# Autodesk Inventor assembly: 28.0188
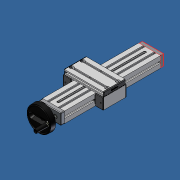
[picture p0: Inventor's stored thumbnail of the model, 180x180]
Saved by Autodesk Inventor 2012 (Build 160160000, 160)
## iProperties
Created: 2007-06
Part Number: 28.0188
Document SubType Name: Assembly
Designer: Andy Moles
Description: ADJUSTING UNIT VEN 45X90 F
Author: Andy Moles
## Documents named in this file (19)
- C:\Andys Backup Data\ANDY'S INVENTOR\INVENTOR LIBRARIES\PARTS LIBRARY\READY FOR USE MODULES LG\28.0188 ADJUSTING UNIT VEN 45X90 F.iam
- C:\Andys Backup Data\ANDY'S INVENTOR\INVENTOR LIBRARIES\PARTS LIBRARY\READY FOR USE MODULES LG\SUBCOMPONENTS\28.0200 BEARING PLATE 45X90 HANDWHEEL SIDE.ipt
- C:\Andys Backup Data\ANDY'S INVENTOR\INVENTOR LIBRARIES\PARTS LIBRARY\READY FOR USE MODULES LG\SUBCOMPONENTS\50.1264 BALL BEARING 10X30X9 6200 2RS DIN 625.ipt
- C:\Andys Backup Data\ANDY'S INVENTOR\INVENTOR LIBRARIES\PARTS LIBRARY\READY FOR USE MODULES LG\SUBCOMPONENTS\28.0201 BEARING PLATE 45X90 IDLER SIDE.ipt
- C:\Andys Backup Data\ANDY'S INVENTOR\INVENTOR LIBRARIES\PARTS LIBRARY\READY FOR USE MODULES LG\SUBCOMPONENTS\28.0204 HANDWHEEL 100mm.iam
- C:\Andys Backup Data\ANDY'S INVENTOR\INVENTOR LIBRARIES\PARTS LIBRARY\FASTENING ELEMENTS\NUTS\21.1351 M8 SQUARE NUT.ipt
- C:\Andys Backup Data\ANDY'S INVENTOR\INVENTOR LIBRARIES\PARTS LIBRARY\FASTENING ELEMENTS\SCREWS CAP\21.1204 M8X25.ipt
- C:\Andys Backup Data\ANDY'S INVENTOR\INVENTOR LIBRARIES\PARTS LIBRARY\READY FOR USE MODULES LG\SUBCOMPONENTS\28.0215_1.ipt
- C:\Andys Backup Data\ANDY'S INVENTOR\INVENTOR LIBRARIES\PARTS LIBRARY\FASTENING ELEMENTS\WASHERS\21.1326 DISC SPRING 20.ipt
- C:\Andys Backup Data\ANDY'S INVENTOR\INVENTOR LIBRARIES\PARTS LIBRARY\READY FOR USE MODULES LG\SUBCOMPONENTS\28.0221 ACME SCREW 16X4.ipt
- C:\Andys Backup Data\ANDY'S INVENTOR\INVENTOR LIBRARIES\PARTS LIBRARY\READY FOR USE MODULES LG\SUBCOMPONENTS\28.0224_1 LWN 32X45-90 90X19-NSC.ipt
- C:\Andys Backup Data\ANDY'S INVENTOR\INVENTOR LIBRARIES\PARTS LIBRARY\READY FOR USE MODULES LG\SUBCOMPONENTS\28.0126 SLIDE 45X32.ipt
- C:\Andys Backup Data\ANDY'S INVENTOR\INVENTOR LIBRARIES\PARTS LIBRARY\READY FOR USE MODULES LG\SUBCOMPONENTS\28.0257 BRONZE NUT 16X4 NOTCHED.ipt
- C:\Andys Backup Data\ANDY'S INVENTOR\INVENTOR LIBRARIES\PARTS LIBRARY\READY FOR USE MODULES LG\SUBCOMPONENTS\28.0254 NUT SLIDE CONNECTOR 16.ipt
- C:\Andys Backup Data\ANDY'S INVENTOR\INVENTOR LIBRARIES\PARTS LIBRARY\FASTENING ELEMENTS\SCREWS CAP\21.1200 M8X16.ipt
- C:\Andys Backup Data\ANDY'S INVENTOR\INVENTOR LIBRARIES\PARTS LIBRARY\FASTENING ELEMENTS\SCREWS CAP\21.1235 M5X16.ipt
- C:\Andys Backup Data\ANDY'S INVENTOR\INVENTOR LIBRARIES\PARTS LIBRARY\END CAPS\22.1014_1 END CAP 90X19 GRAY.ipt
- C:\Andys Backup Data\ANDY'S INVENTOR\INVENTOR LIBRARIES\PARTS LIBRARY\END CAPS\22.1003_1 END CAP 45x32 Z Gray.iam
- C:\Andys Backup Data\ANDY'S INVENTOR\INVENTOR LIBRARIES\PARTS LIBRARY\COMPONENTS LG\22.1095 SLIDE RAIL LN.iam
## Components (36 placed, 18 different names)
1. 28.0215_1:1 — Flush:9, Mate:9, Flush:10, Mate:10, Flush:11, Flush:12, Angle:2, Mate:13, Flush:13, Flush:14, Mate:26, Mate:27
2. 28.0200 BEARING PLATE 45X90 HANDWHEEL SIDE:1 — Insert:4, Insert:6, Insert:7, Insert:11, Angle:2, Mate:13, Flush:13, Flush:14
3. 50.1264 10X30X9 6200 2RS DIN 625 BALL BEARING:1 — Insert:11
4. 50.1264 10X30X9 6200 2RS DIN 625 BALL BEARING:2 — Insert:10, Insert:14
5. 28.0201 BEARING PLATE 45X90 IDLER SIDE:1 — Insert:8, Insert:9, Insert:10, Mate:10, Flush:11, Flush:12
6. 28.0204 HANDWHEEL 100mm:1 [sub-assembly] — Insert:4, Angle:3
7. 21.1204  M8 x 25:1 — Insert:6
8. 21.1204  M8 x 25:2 — Insert:7
9. 21.1204  M8 x 25:3 — Insert:8
10. 21.1204  M8 x 25:4 — Insert:9
11. 21.1326 DISC SPRING 20:1 — Insert:13, Insert:14
12. 21.1326 DISC SPRING 20:2 — Insert:12
13. 28.0221 ACME SCREW 16X4:1 — Insert:12, Insert:13, Angle:3, Mate:25
14. 28.0224_1 LWN 32X45-90 90X19-NSC:1 — Insert:15, Angle:4, Insert:16, Insert:17, Insert:18, Insert:19, Insert:20, Insert:21, Insert:22, Insert:23, Angle:5, Angle:6, Angle:7, Angle:8, Mate:14, Flush:15, Mate:16, Flush:16, Insert:24, Insert:25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
15. 28.0126 SLIDE 45X32:1 — Mate:16, Flush:16, Mate:17, Insert:27, Insert:28, Angle:10, Angle:11, Mate:22, Mate:23
16. 28.0126 SLIDE 45X32:2 — Mate:14, Mate:15, Flush:15, Insert:26, Insert:29, Angle:9, Angle:12, Mate:20, Mate:21
17. 28.0257 BRONZE NUT 16X4 NOTCHED:1 — Mate:24, Angle:13, Mate:25
18. 28.0254 NUT SLIDE CONNECTOR 16:1 — Insert:15, Angle:4, Mate:24, Angle:13
19. 21.1200 M8 x 16:1 — Insert:16, Mate:17
20. 21.1200 M8 x 16:2 — Insert:17
21. 21.1200 M8 x 16:3 — Insert:18, Mate:15
22. 21.1200 M8 x 16:4 — Insert:19
23. 21.1351 M8 SQUARE NUT:2 — Insert:20, Angle:8
24. 21.1351 M8 SQUARE NUT:3 — Insert:21, Angle:7
25. 21.1351 M8 SQUARE NUT:4 — Insert:22, Angle:6
26. 21.1351 M8 SQUARE NUT:5 — Insert:23, Angle:5
27. 21.1235  M5 x 16:1 — Insert:24
28. 21.1235  M5 x 16:2 — Insert:25
29. 22.1014_1 END CAP 90X19 GRAY:1 — Mate:18, Flush:17, Flush:18
30. 22.1014_1 END CAP 90X19 GRAY:2 — Mate:19, Flush:19, Flush:20
31. 22.1003\1 END CAP 45x32 Z Gray:1 [sub-assembly] — Insert:26, Angle:12
32. 22.1003\1 END CAP 45x32 Z Gray:2 [sub-assembly] — Insert:29, Angle:9
33. 22.1003\1 END CAP 45x32 Z Gray:3 [sub-assembly] — Insert:27, Angle:11
34. 22.1003\1 END CAP 45x32 Z Gray:4 [sub-assembly] — Insert:28, Angle:10
35. 22.1095 SLIDE RAIL LN:1 [sub-assembly] — Mate:20, Flush:21, Mate:21, Mate:26, Mate:27
36. 22.1095 SLIDE RAIL LN:2 [sub-assembly] — Mate:22, Mate:23, Flush:22
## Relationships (68: Insert 25, Mate 17, Flush 14, Angle 12)
- Insert:4: 28.0200 BEARING PLATE 45X90 HANDWHEEL SIDE:1 ↔ 28.0204 HANDWHEEL 100mm:1
- Insert:6: 28.0200 BEARING PLATE 45X90 HANDWHEEL SIDE:1 ↔ 21.1204  M8 x 25:1
- Insert:7: 28.0200 BEARING PLATE 45X90 HANDWHEEL SIDE:1 ↔ 21.1204  M8 x 25:2
- Insert:8: 28.0201 BEARING PLATE 45X90 IDLER SIDE:1 ↔ 21.1204  M8 x 25:3
- Insert:9: 28.0201 BEARING PLATE 45X90 IDLER SIDE:1 ↔ 21.1204  M8 x 25:4
- Flush:9: 28.0215_1:1
- Mate:9: 28.0215_1:1
- Insert:10: 50.1264 10X30X9 6200 2RS DIN 625 BALL BEARING:2 ↔ 28.0201 BEARING PLATE 45X90 IDLER SIDE:1
- Insert:11: 28.0200 BEARING PLATE 45X90 HANDWHEEL SIDE:1 ↔ 50.1264 10X30X9 6200 2RS DIN 625 BALL BEARING:1
- Flush:10: 28.0215_1:1
- Mate:10: 28.0215_1:1 ↔ 28.0201 BEARING PLATE 45X90 IDLER SIDE:1
- Flush:11: 28.0215_1:1 ↔ 28.0201 BEARING PLATE 45X90 IDLER SIDE:1
- Flush:12: 28.0215_1:1 ↔ 28.0201 BEARING PLATE 45X90 IDLER SIDE:1
- Angle:2: 28.0215_1:1 ↔ 28.0200 BEARING PLATE 45X90 HANDWHEEL SIDE:1
- Mate:13: 28.0215_1:1 ↔ 28.0200 BEARING PLATE 45X90 HANDWHEEL SIDE:1
- Flush:13: 28.0215_1:1 ↔ 28.0200 BEARING PLATE 45X90 HANDWHEEL SIDE:1
- Flush:14: 28.0215_1:1 ↔ 28.0200 BEARING PLATE 45X90 HANDWHEEL SIDE:1
- Insert:12: 21.1326 DISC SPRING 20:2 ↔ 28.0221 ACME SCREW 16X4:1
- Insert:13: 21.1326 DISC SPRING 20:1 ↔ 28.0221 ACME SCREW 16X4:1
- Insert:14: 50.1264 10X30X9 6200 2RS DIN 625 BALL BEARING:2 ↔ 21.1326 DISC SPRING 20:1
- Angle:3: 28.0204 HANDWHEEL 100mm:1 ↔ 28.0221 ACME SCREW 16X4:1
- Insert:15: 28.0224_1 LWN 32X45-90 90X19-NSC:1 ↔ 28.0254 NUT SLIDE CONNECTOR 16:1
- Angle:4: 28.0224_1 LWN 32X45-90 90X19-NSC:1 ↔ 28.0254 NUT SLIDE CONNECTOR 16:1
- Insert:16: 28.0224_1 LWN 32X45-90 90X19-NSC:1 ↔ 21.1200 M8 x 16:1
- Insert:17: 28.0224_1 LWN 32X45-90 90X19-NSC:1 ↔ 21.1200 M8 x 16:2
- Insert:18: 28.0224_1 LWN 32X45-90 90X19-NSC:1 ↔ 21.1200 M8 x 16:3
- Insert:19: 28.0224_1 LWN 32X45-90 90X19-NSC:1 ↔ 21.1200 M8 x 16:4
- Insert:20: 28.0224_1 LWN 32X45-90 90X19-NSC:1 ↔ 21.1351 M8 SQUARE NUT:2
- Insert:21: 28.0224_1 LWN 32X45-90 90X19-NSC:1 ↔ 21.1351 M8 SQUARE NUT:3
- Insert:22: 28.0224_1 LWN 32X45-90 90X19-NSC:1 ↔ 21.1351 M8 SQUARE NUT:4
- Insert:23: 28.0224_1 LWN 32X45-90 90X19-NSC:1 ↔ 21.1351 M8 SQUARE NUT:5
- Angle:5: 28.0224_1 LWN 32X45-90 90X19-NSC:1 ↔ 21.1351 M8 SQUARE NUT:5
- Angle:6: 28.0224_1 LWN 32X45-90 90X19-NSC:1 ↔ 21.1351 M8 SQUARE NUT:4
- Angle:7: 28.0224_1 LWN 32X45-90 90X19-NSC:1 ↔ 21.1351 M8 SQUARE NUT:3
- Angle:8: 28.0224_1 LWN 32X45-90 90X19-NSC:1 ↔ 21.1351 M8 SQUARE NUT:2
- Mate:14: 28.0224_1 LWN 32X45-90 90X19-NSC:1 ↔ 28.0126 SLIDE 45X32:2
- Mate:15: 28.0126 SLIDE 45X32:2 ↔ 21.1200 M8 x 16:3
- Flush:15: 28.0224_1 LWN 32X45-90 90X19-NSC:1 ↔ 28.0126 SLIDE 45X32:2
- Mate:16: 28.0224_1 LWN 32X45-90 90X19-NSC:1 ↔ 28.0126 SLIDE 45X32:1
- Flush:16: 28.0224_1 LWN 32X45-90 90X19-NSC:1 ↔ 28.0126 SLIDE 45X32:1
- Mate:17: 28.0126 SLIDE 45X32:1 ↔ 21.1200 M8 x 16:1
- Insert:24: 28.0224_1 LWN 32X45-90 90X19-NSC:1 ↔ 21.1235  M5 x 16:1
- Insert:25: 28.0224_1 LWN 32X45-90 90X19-NSC:1 ↔ 21.1235  M5 x 16:2
- Mate:18: 28.0224_1 LWN 32X45-90 90X19-NSC:1 ↔ 22.1014_1 END CAP 90X19 GRAY:1
- Flush:17: 28.0224_1 LWN 32X45-90 90X19-NSC:1 ↔ 22.1014_1 END CAP 90X19 GRAY:1
- Flush:18: 28.0224_1 LWN 32X45-90 90X19-NSC:1 ↔ 22.1014_1 END CAP 90X19 GRAY:1
- Mate:19: 28.0224_1 LWN 32X45-90 90X19-NSC:1 ↔ 22.1014_1 END CAP 90X19 GRAY:2
- Flush:19: 28.0224_1 LWN 32X45-90 90X19-NSC:1 ↔ 22.1014_1 END CAP 90X19 GRAY:2
- Flush:20: 28.0224_1 LWN 32X45-90 90X19-NSC:1 ↔ 22.1014_1 END CAP 90X19 GRAY:2
- Insert:26: 28.0126 SLIDE 45X32:2 ↔ 22.1003\1 END CAP 45x32 Z Gray:1
- Insert:27: 28.0126 SLIDE 45X32:1 ↔ 22.1003\1 END CAP 45x32 Z Gray:3
- Insert:28: 28.0126 SLIDE 45X32:1 ↔ 22.1003\1 END CAP 45x32 Z Gray:4
- Insert:29: 28.0126 SLIDE 45X32:2 ↔ 22.1003\1 END CAP 45x32 Z Gray:2
- Angle:9: 28.0126 SLIDE 45X32:2 ↔ 22.1003\1 END CAP 45x32 Z Gray:2
- Angle:10: 28.0126 SLIDE 45X32:1 ↔ 22.1003\1 END CAP 45x32 Z Gray:4
- Angle:11: 28.0126 SLIDE 45X32:1 ↔ 22.1003\1 END CAP 45x32 Z Gray:3
- Angle:12: 28.0126 SLIDE 45X32:2 ↔ 22.1003\1 END CAP 45x32 Z Gray:1
- Mate:20: 28.0126 SLIDE 45X32:2 ↔ 22.1095 SLIDE RAIL LN:1
- Flush:21: 28.0224_1 LWN 32X45-90 90X19-NSC:1 ↔ 22.1095 SLIDE RAIL LN:1
- Mate:21: 28.0126 SLIDE 45X32:2 ↔ 22.1095 SLIDE RAIL LN:1
- Mate:22: 28.0126 SLIDE 45X32:1 ↔ 22.1095 SLIDE RAIL LN:2
- Mate:23: 28.0126 SLIDE 45X32:1 ↔ 22.1095 SLIDE RAIL LN:2
- Flush:22: 28.0224_1 LWN 32X45-90 90X19-NSC:1 ↔ 22.1095 SLIDE RAIL LN:2
- Mate:24: 28.0257 BRONZE NUT 16X4 NOTCHED:1 ↔ 28.0254 NUT SLIDE CONNECTOR 16:1
- Angle:13: 28.0257 BRONZE NUT 16X4 NOTCHED:1 ↔ 28.0254 NUT SLIDE CONNECTOR 16:1
- Mate:25: 28.0221 ACME SCREW 16X4:1 ↔ 28.0257 BRONZE NUT 16X4 NOTCHED:1
- Mate:26: 28.0215_1:1 ↔ 22.1095 SLIDE RAIL LN:1
- Mate:27: 28.0215_1:1 ↔ 22.1095 SLIDE RAIL LN:1
